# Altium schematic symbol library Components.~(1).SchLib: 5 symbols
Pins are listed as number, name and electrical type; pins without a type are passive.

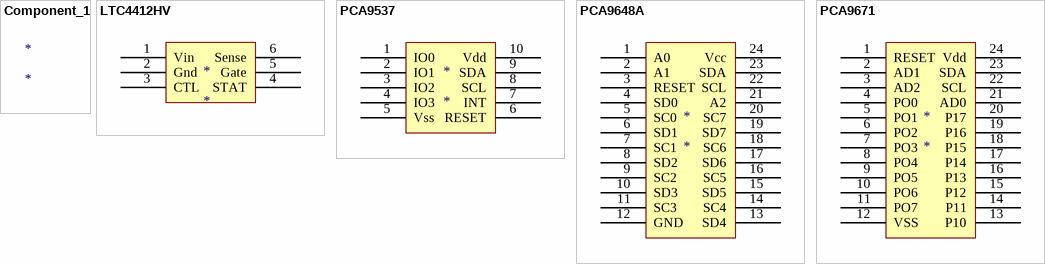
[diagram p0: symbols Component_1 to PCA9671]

## Component_1
designator *

## LTC4412HV
designator *
pins: 1 Vin, 2 Gnd, 3 CTL, 4 STAT, 5 Gate, 6 Sense

## PCA9537
designator *
pins: 1 IO0, 2 IO1, 3 IO2, 4 IO3, 5 Vss, 6 RESET, 7 INT, 8 SCL, 9 SDA, 10 Vdd

## PCA9648A
designator *
pins: 1 A0, 2 A1, 3 RESET, 4 SD0, 5 SC0, 6 SD1, 7 SC1, 8 SD2, 9 SC2, 10 SD3, 11 SC3, 12 GND, 13 SD4, 14 SC4, 15 SD5, 16 SC5, 17 SD6, 18 SC6, 19 SD7, 20 SC7, 21 A2, 22 SCL, 23 SDA, 24 Vcc

## PCA9671
designator *
pins: 1 RESET, 2 AD1, 3 AD2, 4 PO0, 5 PO1, 6 PO2, 7 PO3, 8 PO4, 9 PO5, 10 PO6, 11 PO7, 12 VSS, 13 P10, 14 P11, 15 P12, 16 P13, 17 P14, 18 P15, 19 P16, 20 P17, 21 AD0, 22 SCL, 23 SDA, 24 Vdd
